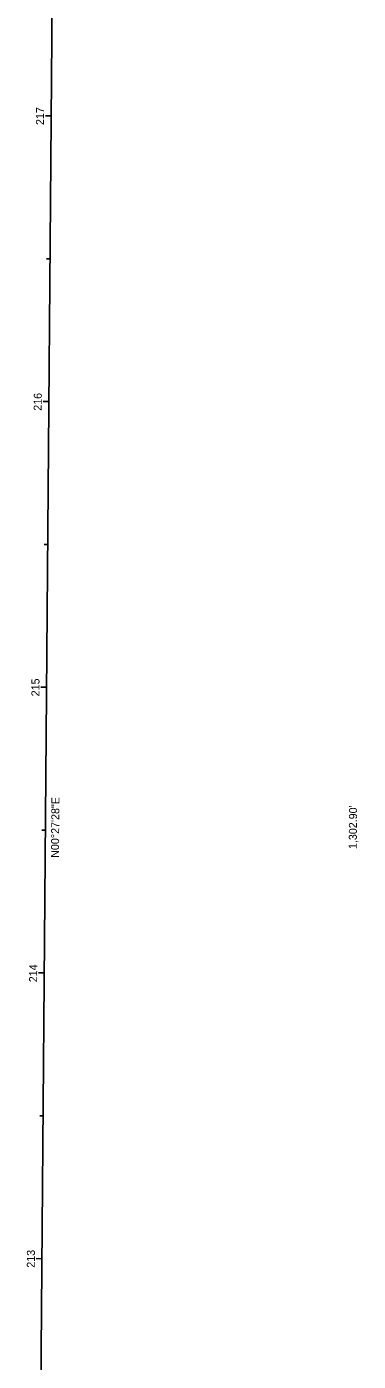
# Model space of a CAD drawing. Extents: x 1504466 to 1504712, y 322450 to 329957.
# Drawn here: x 1504550.8 to 1504666.8, y 322916.7 to 323383.8 of the extents above; entities that cross this region are included whole.
import ezdxf

# ---------------------------------------------------------------- set-up
doc = ezdxf.new("R2010")
doc.units = 0
for name, color, linetype in [('GE_X_Alignment', 7, 'Continuous'), ('GE_X_Alignment_100_Bearings', 7, 'Continuous'), ('GE_X_Alignment_100_Distances', 7, 'Continuous'), ('GE_X_Alignment_100_Stations', 7, 'Continuous'), ('GE_X_Alignment_500_Bearings', 7, 'Continuous'), ('GE_X_Alignment_500_Distances', 7, 'Continuous'), ('GE_X_Alignment_500_Stations', 7, 'Continuous')]:
    doc.layers.add(name, color=color, linetype=linetype)

msp = doc.modelspace()

# ---------------------------------------------------------------- linework, layer by layer
at = {"layer": 'GE_X_Alignment'}
msp.add_line((1504552.13, 322452.59), (1504562.54, 323755.45), dxfattribs=at)
at = {"layer": 'GE_X_Alignment_100_Stations'}
for p, q in [((1504559.32, 323352.56), (1504557.32, 323352.58)), ((1504558.92, 323302.56), (1504557.72, 323302.57)), ((1504558.52, 323252.57), (1504556.52, 323252.58)), ((1504558.12, 323202.57), (1504556.92, 323202.58)), ((1504557.72, 323152.57), (1504555.72, 323152.59)), ((1504557.32, 323102.57), (1504556.12, 323102.58)), ((1504556.92, 323052.57), (1504554.92, 323052.59)), ((1504556.53, 323002.57), (1504555.33, 323002.58)), ((1504556.13, 322952.58), (1504554.13, 322952.59))]:
    msp.add_line(p, q, dxfattribs=at)
at = {"layer": 'GE_X_Alignment_500_Stations'}
for p, q in [((1504559.32, 323352.56), (1504558.12, 323352.57)), ((1504558.52, 323252.57), (1504557.32, 323252.58)), ((1504557.72, 323152.57), (1504555.72, 323152.59)), ((1504556.92, 323052.57), (1504555.72, 323052.58)), ((1504556.13, 322952.58), (1504554.93, 322952.59))]:
    msp.add_line(p, q, dxfattribs=at)

# ---------------------------------------------------------------- texts
at = {"layer": 'GE_X_Alignment_100_Bearings'}
msp.add_text('N00°27\'28"E', height=2.8, rotation=89.5421, dxfattribs=at).set_placement((1504562.05, 323092.87))
at = {"layer": 'GE_X_Alignment_100_Distances'}
msp.add_text("1,302.90'", height=2.8, rotation=89.5421, dxfattribs=at).set_placement((1504666.28, 323095.93))
at = {"layer": 'GE_X_Alignment_100_Stations'}
for s, p in [('217', (1504556.8, 323349.34)), ('216', (1504556, 323249.33)), ('215', (1504555.2, 323149.38)), ('214', (1504554.4, 323049.31)), ('213', (1504553.6, 322949.4))]:
    msp.add_text(s, height=2.8, rotation=89.5421, dxfattribs=at).set_placement(p)
at = {"layer": 'GE_X_Alignment_500_Bearings'}
msp.add_text('N00°27\'28"E', height=2.8, rotation=89.5421, dxfattribs=at).set_placement((1504562.05, 323092.87))
at = {"layer": 'GE_X_Alignment_500_Distances'}
msp.add_text("1,302.90'", height=2.8, rotation=89.5421, dxfattribs=at).set_placement((1504666.28, 323095.93))
at = {"layer": 'GE_X_Alignment_500_Stations'}
msp.add_text('215', height=2.8, rotation=89.5421, dxfattribs=at).set_placement((1504555.2, 323149.38))

doc.saveas('drawing.dxf')
